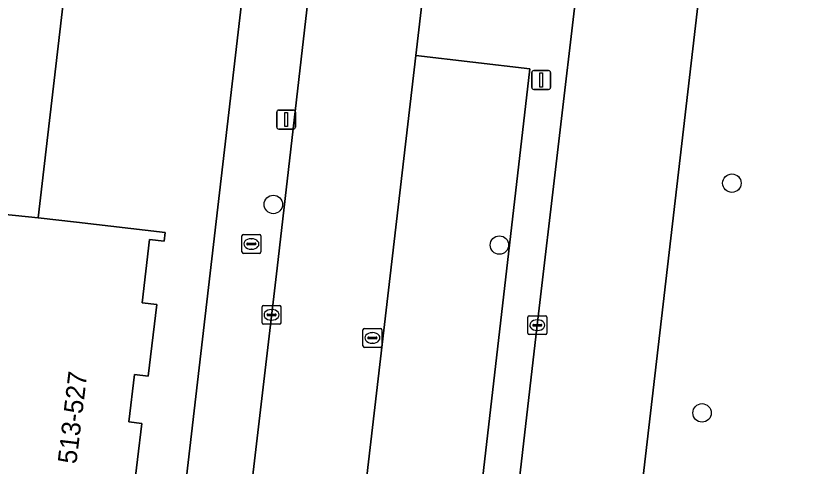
# Model space of a CAD drawing. Extents: x 160856 to 161310, y 384024 to 384878.
# Drawn here: x 161229.52 to 161271.23, y 384534.96 to 384558.85 of the extents above; entities that cross this region are included whole.
import ezdxf

# ---------------------------------------------------------------- set-up
doc = ezdxf.new("R2010")
doc.units = 0
for name, color, linetype in [('IMGEO_Berm_groen', 7, 'Continuous'), ('IMGEO_Boom', 7, 'Continuous'), ('IMGEO_Brandkraan', 7, 'Continuous'), ('IMGEO_Erf', 7, 'Continuous'), ('IMGEO_Kolk', 7, 'Continuous'), ('IMGEO_Lichtmast', 7, 'Continuous'), ('IMGEO_Pand', 7, 'Continuous'), ('IMGEO_Pand_nummerreeks', 7, 'Continuous'), ('IMGEO_Parkeervlak_open', 7, 'Continuous'), ('IMGEO_Rijbaan_lokaal_gesloten', 7, 'Continuous'), ('IMGEO_Rijbaan_lokaal_open', 7, 'Continuous'), ('IMGEO_Voetpad_open', 7, 'Continuous')]:
    doc.layers.add(name, color=color, linetype=linetype)

msp = doc.modelspace()

# ---------------------------------------------------------------- linework, layer by layer
at = {"layer": 'IMGEO_Berm_groen'}
for points in [[(161271.226, 384656.034), (161271.075, 384657.442), (161268.546, 384657.7), (161262.738, 384608.287), (161261.545, 384598.151), (161258.141, 384567.697), (161257.931, 384565.814), (161257.361, 384560.886), (161251.303, 384561.613), (161250.737, 384556.74), (161256.785, 384556.041), (161251.596, 384511.132), (161250.377, 384500), (161238.15, 384396.266), (161238.006, 384395.04), (161236.799, 384395.17)], [(161254.83, 384522.177), (161257.178, 384542.439), (161259.33, 384560.777), (161261.579, 384580.114), (161261.966, 384583.337)], [(161269.166, 384580.645), (161268.148, 384576.401), (161267.446, 384572.759), (161266.816, 384568.826), (161266.33, 384564.879), (161259.354, 384504.899), (161254.88, 384466.32), (161245.611, 384386.656)]]:
    msp.add_lwpolyline(points, dxfattribs=at)
at = {"layer": 'IMGEO_Boom'}
for centre in [(161267.494, 384549.972), (161243.181, 384548.842), (161255.169, 384546.689), (161265.912, 384537.789)]:
    msp.add_circle(centre, 0.489, dxfattribs=at)
at = {"layer": 'IMGEO_Brandkraan'}
for p, q in [((161241.516, 384546.322), (161241.516, 384547.174)), ((161241.591, 384547.248), (161242.443, 384547.248)), ((161242.004, 384547.028), (161242.029, 384547.028)), ((161242.517, 384547.174), (161242.517, 384546.322)), ((161241.775, 384546.742), (161241.775, 384546.754)), ((161242.213, 384546.705), (161241.815, 384546.705)), ((161241.818, 384546.791), (161242.216, 384546.791)), ((161242.259, 384546.754), (161242.259, 384546.742)), ((161242.443, 384546.248), (161241.591, 384546.248)), ((161242.027, 384546.468), (161242.002, 384546.468))]:
    msp.add_line(p, q, dxfattribs=at)
for points in [[(161241.516, 384546.322), (161241.516, 384547.174)], [(161241.591, 384547.248), (161242.443, 384547.248)], [(161242.517, 384547.174), (161242.517, 384546.322)], [(161242.443, 384546.248), (161241.591, 384546.248)]]:
    msp.add_lwpolyline(points, dxfattribs=at)
for centre, radius, start, end in [((161241.593, 384547.172), 0.0765, 91.552, 178.448), ((161241.593, 384547.172), 0.0765, 91.552, 178.448), ((161242.441, 384547.172), 0.0765, 1.552, 88.448), ((161242.441, 384547.172), 0.0765, 1.552, 88.448), ((161241.815, 384546.751), 0.0403, 85.8775, 175.7526), ((161241.812, 384546.741), 0.0366, 178.938, 274.7102), ((161242.216, 384546.748), 0.043, 264.8664, 352.4533), ((161242.22, 384546.753), 0.0386, 1.7309, 96.639), ((161241.593, 384546.324), 0.0765, 181.552, 268.448), ((161241.593, 384546.324), 0.0765, 181.552, 268.448), ((161242.441, 384546.324), 0.0765, 271.552, 358.448), ((161242.441, 384546.324), 0.0765, 271.552, 358.448)]:
    msp.add_arc(centre, radius, start, end, dxfattribs=at)
for centre, major_axis, ratio, start_param, end_param in [((161242.003, 384546.748), (-0.387, 0.002), 0.722429, 4.712389, 7.853982), ((161242.028, 384546.748), (-0.39, 0.002), 0.717154, 1.570796, 4.712389)]:
    msp.add_ellipse(centre, major_axis=major_axis, ratio=ratio, start_param=start_param, end_param=end_param, dxfattribs=at)
at = {"layer": 'IMGEO_Erf'}
for points in [[(161234.582, 384500), (161242.07, 384564.539)], [(161232.592, 384564.236), (161230.709, 384548.137), (161232.751, 384547.898), (161237.443, 384547.35), (161237.389, 384546.889), (161236.617, 384546.979), (161236.224, 384543.627), (161236.996, 384543.537), (161236.552, 384539.735), (161235.817, 384539.821), (161235.524, 384537.311), (161236.204, 384537.232), (161235.756, 384533.408)]]:
    msp.add_lwpolyline(points, dxfattribs=at)
at = {"layer": 'IMGEO_Kolk'}
for p, q in [((161242.586, 384542.56), (161242.586, 384543.412)), ((161242.661, 384543.486), (161243.513, 384543.486)), ((161243.074, 384543.266), (161243.099, 384543.266)), ((161243.587, 384543.412), (161243.587, 384542.56)), ((161242.845, 384542.98), (161242.845, 384542.992)), ((161243.283, 384542.943), (161242.885, 384542.943)), ((161242.888, 384543.029), (161243.286, 384543.029)), ((161243.329, 384542.992), (161243.329, 384542.98)), ((161256.677, 384542.013), (161256.677, 384542.865)), ((161256.752, 384542.939), (161257.604, 384542.939)), ((161257.678, 384542.865), (161257.678, 384542.013)), ((161243.513, 384542.486), (161242.661, 384542.486)), ((161243.097, 384542.706), (161243.072, 384542.706)), ((161256.936, 384542.433), (161256.936, 384542.445)), ((161256.979, 384542.482), (161257.377, 384542.482)), ((161257.165, 384542.719), (161257.19, 384542.719)), ((161257.42, 384542.445), (161257.42, 384542.433)), ((161247.934, 384541.337), (161247.934, 384542.189)), ((161248.009, 384542.263), (161248.861, 384542.263)), ((161248.422, 384542.043), (161248.447, 384542.043)), ((161248.935, 384542.189), (161248.935, 384541.337)), ((161257.374, 384542.396), (161256.976, 384542.396)), ((161257.188, 384542.159), (161257.163, 384542.159)), ((161248.193, 384541.757), (161248.193, 384541.769)), ((161248.631, 384541.72), (161248.233, 384541.72)), ((161248.236, 384541.806), (161248.634, 384541.806)), ((161248.677, 384541.769), (161248.677, 384541.757)), ((161257.604, 384541.939), (161256.752, 384541.939)), ((161248.861, 384541.263), (161248.009, 384541.263)), ((161248.445, 384541.483), (161248.42, 384541.483))]:
    msp.add_line(p, q, dxfattribs=at)
for points in [[(161242.586, 384542.56), (161242.586, 384543.412)], [(161242.661, 384543.486), (161243.513, 384543.486)], [(161243.587, 384543.412), (161243.587, 384542.56)], [(161256.677, 384542.013), (161256.677, 384542.865)], [(161256.752, 384542.939), (161257.604, 384542.939)], [(161257.678, 384542.865), (161257.678, 384542.013)], [(161243.513, 384542.486), (161242.661, 384542.486)], [(161247.934, 384541.337), (161247.934, 384542.189)], [(161248.009, 384542.263), (161248.861, 384542.263)], [(161248.935, 384542.189), (161248.935, 384541.337)], [(161257.604, 384541.939), (161256.752, 384541.939)], [(161248.861, 384541.263), (161248.009, 384541.263)]]:
    msp.add_lwpolyline(points, dxfattribs=at)
for centre, radius, start, end in [((161242.663, 384543.41), 0.0765, 91.552, 178.448), ((161242.663, 384543.41), 0.0765, 91.552, 178.448), ((161243.511, 384543.41), 0.0765, 1.552, 88.448), ((161243.511, 384543.41), 0.0765, 1.552, 88.448), ((161242.885, 384542.989), 0.0403, 85.8775, 175.7526), ((161242.882, 384542.979), 0.0366, 178.938, 274.7102), ((161243.286, 384542.986), 0.043, 264.8664, 352.4533), ((161243.29, 384542.991), 0.0386, 1.7309, 96.639), ((161256.754, 384542.863), 0.0765, 91.552, 178.448), ((161256.754, 384542.863), 0.0765, 91.552, 178.448), ((161257.602, 384542.863), 0.0765, 1.552, 88.448), ((161257.602, 384542.863), 0.0765, 1.552, 88.448), ((161242.663, 384542.562), 0.0765, 181.552, 268.448), ((161242.663, 384542.562), 0.0765, 181.552, 268.448), ((161243.511, 384542.562), 0.0765, 271.552, 358.448), ((161243.511, 384542.562), 0.0765, 271.552, 358.448), ((161256.976, 384542.442), 0.0403, 85.8775, 175.7526), ((161256.973, 384542.432), 0.0366, 178.938, 274.7102), ((161257.377, 384542.439), 0.043, 264.8664, 352.4533), ((161257.381, 384542.444), 0.0386, 1.7309, 96.639), ((161248.011, 384542.187), 0.0765, 91.552, 178.448), ((161248.011, 384542.187), 0.0765, 91.552, 178.448), ((161248.859, 384542.187), 0.0765, 1.552, 88.448), ((161248.859, 384542.187), 0.0765, 1.552, 88.448), ((161256.754, 384542.015), 0.0765, 181.552, 268.448), ((161256.754, 384542.015), 0.0765, 181.552, 268.448), ((161257.602, 384542.015), 0.0765, 271.552, 358.448), ((161257.602, 384542.015), 0.0765, 271.552, 358.448), ((161248.233, 384541.766), 0.0403, 85.8775, 175.7526), ((161248.23, 384541.756), 0.0366, 178.938, 274.7102), ((161248.634, 384541.763), 0.043, 264.8664, 352.4533), ((161248.638, 384541.768), 0.0386, 1.7309, 96.639), ((161248.011, 384541.339), 0.0765, 181.552, 268.448), ((161248.011, 384541.339), 0.0765, 181.552, 268.448), ((161248.859, 384541.339), 0.0765, 271.552, 358.448), ((161248.859, 384541.339), 0.0765, 271.552, 358.448)]:
    msp.add_arc(centre, radius, start, end, dxfattribs=at)
for centre, major_axis, ratio, start_param, end_param in [((161243.073, 384542.986), (-0.387, 0.002), 0.722429, 4.712389, 7.853982), ((161243.098, 384542.986), (-0.39, 0.002), 0.717154, 1.570796, 4.712389), ((161257.164, 384542.439), (-0.387, 0.002), 0.722429, 4.712389, 7.853982), ((161257.189, 384542.439), (-0.39, 0.002), 0.717154, 1.570796, 4.712389), ((161248.421, 384541.763), (-0.387, 0.002), 0.722429, 4.712389, 7.853982), ((161248.446, 384541.763), (-0.39, 0.002), 0.717154, 1.570796, 4.712389)]:
    msp.add_ellipse(centre, major_axis=major_axis, ratio=ratio, start_param=start_param, end_param=end_param, dxfattribs=at)
at = {"layer": 'IMGEO_Lichtmast'}
for p, q in [((161256.887, 384555.043), (161256.887, 384555.843)), ((161256.887, 384555.843), (161256.887, 384555.043)), ((161256.987, 384555.943), (161257.777, 384555.943)), ((161257.777, 384555.943), (161256.987, 384555.943)), ((161257.877, 384555.843), (161257.877, 384555.043)), ((161257.877, 384555.043), (161257.877, 384555.843)), ((161257.777, 384554.943), (161256.987, 384554.943)), ((161256.987, 384554.943), (161257.777, 384554.943)), ((161243.364, 384552.944), (161243.364, 384553.744)), ((161243.364, 384553.744), (161243.364, 384552.944)), ((161243.464, 384553.844), (161244.254, 384553.844)), ((161244.254, 384553.844), (161243.464, 384553.844)), ((161244.354, 384553.744), (161244.354, 384552.944)), ((161244.354, 384552.944), (161244.354, 384553.744)), ((161244.254, 384552.844), (161243.464, 384552.844)), ((161243.464, 384552.844), (161244.254, 384552.844))]:
    msp.add_line(p, q, dxfattribs=at)
for points in [[(161257.307, 384555.818), (161257.457, 384555.818), (161257.457, 384555.068), (161257.307, 384555.068), (161257.307, 384555.818)], [(161243.784, 384553.719), (161243.934, 384553.719), (161243.934, 384552.969), (161243.784, 384552.969), (161243.784, 384553.719)]]:
    msp.add_lwpolyline(points, dxfattribs=at)
for centre, start, end in [((161256.987, 384555.843), 90, 180), ((161256.987, 384555.843), 90, 180), ((161257.777, 384555.843), 0, 90), ((161257.777, 384555.843), 360, 90), ((161256.987, 384555.043), 180, 270), ((161256.987, 384555.043), 180, 270), ((161257.777, 384555.043), 270, 0), ((161257.777, 384555.043), 270, 0), ((161243.464, 384553.744), 90, 180), ((161243.464, 384553.744), 90, 180), ((161244.254, 384553.744), 0, 90), ((161244.254, 384553.744), 360, 90), ((161243.464, 384552.944), 180, 270), ((161243.464, 384552.944), 180, 270), ((161244.254, 384552.944), 270, 0), ((161244.254, 384552.944), 270, 0)]:
    msp.add_arc(centre, 0.1, start, end, dxfattribs=at)
at = {"layer": 'IMGEO_Pand'}
for points in [[(161222.192, 384560.826), (161221.133, 384551.765), (161221.906, 384551.675), (161221.66, 384549.565), (161221.016, 384549.64), (161220.972, 384549.268), (161221.799, 384549.171), (161221.688, 384548.215), (161223.52, 384548.001), (161223.624, 384548.891), (161225.533, 384548.667), (161230.709, 384548.137), (161232.592, 384564.236)], [(161223.524, 384531.132), (161235.341, 384529.749), (161235.359, 384529.901), (161234.613, 384529.988), (161235.024, 384533.494), (161235.756, 384533.408), (161236.204, 384537.232), (161235.524, 384537.311), (161235.817, 384539.821), (161236.552, 384539.735), (161236.996, 384543.537), (161236.224, 384543.627), (161236.617, 384546.979), (161237.389, 384546.889), (161237.443, 384547.35), (161232.751, 384547.898), (161230.709, 384548.137), (161225.533, 384548.667)]]:
    msp.add_lwpolyline(points, dxfattribs=at)
at = {"layer": 'IMGEO_Parkeervlak_open'}
for points in [[(161256.785, 384556.041), (161250.737, 384556.74), (161231.686, 384393.141)], [(161236.799, 384395.17), (161238.006, 384395.04), (161238.15, 384396.266), (161250.377, 384500), (161251.596, 384511.132), (161256.785, 384556.041)]]:
    msp.add_lwpolyline(points, dxfattribs=at)
at = {"layer": 'IMGEO_Rijbaan_lokaal_gesloten'}
for points in [[(161261.966, 384583.337), (161261.579, 384580.114), (161259.33, 384560.777), (161257.178, 384542.439), (161254.83, 384522.177), (161252.438, 384501.823), (161250.03, 384480.998), (161247.876, 384462.682), (161246.021, 384446.828), (161243.88, 384428.499), (161241.912, 384411.162), (161239.6, 384390.894), (161238.653, 384382.516), (161238.178, 384378.283), (161237.763, 384375.367), (161237.563, 384374.434), (161237.479, 384374.076), (161237.25, 384373.157), (161237.241, 384373.124), (161237.099, 384372.576), (161236.892, 384371.866), (161236.493, 384370.578)], [(161245.611, 384386.656), (161254.88, 384466.32), (161259.354, 384504.899), (161266.33, 384564.879), (161266.816, 384568.826), (161267.446, 384572.759), (161268.148, 384576.401), (161269.166, 384580.645)]]:
    msp.add_lwpolyline(points, dxfattribs=at)
at = {"layer": 'IMGEO_Rijbaan_lokaal_open'}
for points in [[(161250.737, 384556.74), (161251.303, 384561.613), (161251.981, 384567.454), (161262.507, 384658.314)], [(161253.842, 384635.509), (161253.738, 384634.519), (161250.766, 384609.622), (161249.855, 384601.831), (161243.381, 384545.472), (161239.778, 384514.805), (161238.057, 384500), (161237.777, 384496.96), (161237.656, 384495.995), (161237.846, 384495.256), (161238.878, 384493.86)], [(161236.821, 384488.628), (161236.635, 384487.009), (161235.532, 384478.284), (161231.826, 384447.259), (161225.155, 384389.562), (161224.63, 384384.341), (161229.978, 384383.71), (161230.652, 384383.631), (161231.223, 384389.168), (161231.686, 384393.141), (161250.737, 384556.74)]]:
    msp.add_lwpolyline(points, dxfattribs=at)
at = {"layer": 'IMGEO_Voetpad_open'}
msp.add_lwpolyline([(161242.07, 384564.539), (161234.582, 384500), (161233.969, 384494.717), (161237.656, 384495.995), (161237.777, 384496.96), (161238.057, 384500), (161239.778, 384514.805), (161243.381, 384545.472), (161249.855, 384601.831)], dxfattribs=at)

# ---------------------------------------------------------------- texts
at = {"layer": 'IMGEO_Pand_nummerreeks'}
msp.add_text('513-527', height=1, rotation=83.1591, dxfattribs=at).set_placement((161232.735, 384535.047))

doc.saveas('drawing.dxf')
